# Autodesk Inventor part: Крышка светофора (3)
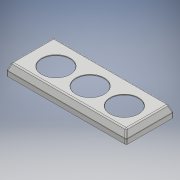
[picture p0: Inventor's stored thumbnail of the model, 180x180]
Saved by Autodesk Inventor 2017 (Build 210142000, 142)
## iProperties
Part Number: Крышка светофора (3)
Material: Типовые
Document SubType Name: Modeling
Designer: Система Знаний
Density: 1 g/cm^3
Appearance: По умолчанию
Author: Система Знаний
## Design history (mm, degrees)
sketch "Эскиз1"
  geometry: L1 (0, 0)-(474, 0); L2 (474, 0)-(474, -175); L3 (474, -175)-(0, -175); L4 (0, -175)-(0, 0)
  constraints: 8 end point, 2 parallel, 1 horizontal, 1 perpendicular
  dimensions: "d0" = 474 distance of L2.end L3.end; "d1" = 175 distance of L1.end L2.end
extrude "Выдавливание1" new body sketch "Эскиз1" distance "d2" = 26.7; taper "d3" = 0 deg
feature "НаклГрань1" dims angle "d4" = 20.3 deg
sketch "Эскиз4"
  geometry: L1 (9.877, 9.877)-(-483.877, 9.877) reference; L2 (-483.877, 9.877)-(-483.877, -184.877) reference; L3 (9.877, 9.877)-(-483.877, 9.877); L4 (-483.877, 9.877)-(-483.877, -184.877); L5 (-483.877, -184.877)-(9.877, -184.877); L6 (9.877, -184.877)-(9.877, 9.877); 1 further point
  constraints: 8 end point, 2 parallel, 1 horizontal, 1 perpendicular
extrude "Выдавливание4" join sketch "Эскиз4" distance "d9" = 20; taper "d10" = 0 deg
feature "Оболочка1" dims "d11" = 1.7
sketch "Эскиз5"
  geometry: L1 (0, -175)-(0, 0) reference; L2 (0, 0)-(474, 0) reference; L3 (0, -175)-(474, -175); L4 (474, -175)-(474, 0); L5 (474, 0)-(0, 0); L6 (0, 0)-(0, -175)
  constraints: 8 end point, 2 parallel, 1 horizontal, 1 perpendicular
extrude "Выдавливание5" join sketch "Эскиз5" distance "d12" = 1.3; taper "d13" = -20.3 deg
fillet "Сопряжение2" dims "d15" = 6
fillet "Сопряжение3" dims "d16" = 6
fillet "Сопряжение5" dims "d18" = 4
fillet "Сопряжение6" dims "d19" = 2
sketch "Эскиз6"
  geometry: L1 (469.341, -4.659)-(474.969, -4.659) reference; C1 r 58 at (247, -97); C2 r 58 at (106, -97); C3 r 58 at (388, -97); 5 further points
  constraints: 3 centre point, 3 coincident
  dimensions: "d20" = 116 diameter of C1; "d23" = 116 diameter of C2; "d24" = 116 diameter of C3
hole "Отверстие1" sketch "Эскиз6" at (247, -97), (388, -97), (106, -97) diameter "d25" = 116; stored, may be unused: countersink angle "d29" = 90 deg, drill point angle "d31" = 118 deg; dims "d26" = 6, "d27" = 118, "d28" = 2, "d30" = 8
sketch "Эскиз8"
  geometry: C1 r 5 at (40, -10); C2 r 5 at (155, -10); C3 r 5 at (270, -10); 5 further points
  constraints: 3 centre point, 3 coincident
  dimensions: "d38" = 10 diameter of C1; "d39" = 10 diameter of C2; "d40" = 10 diameter of C3
hole "Отверстие2" sketch "Эскиз8" at (270, -10), (155, -10), (40, -10) diameter "d41" = 10; stored, may be unused: countersink angle "d45" = 90 deg, drill point angle "d47" = 118 deg; dims "d42" = 6, "d43" = 11, "d44" = 2, "d46" = 8
node "Твердое тело1"
